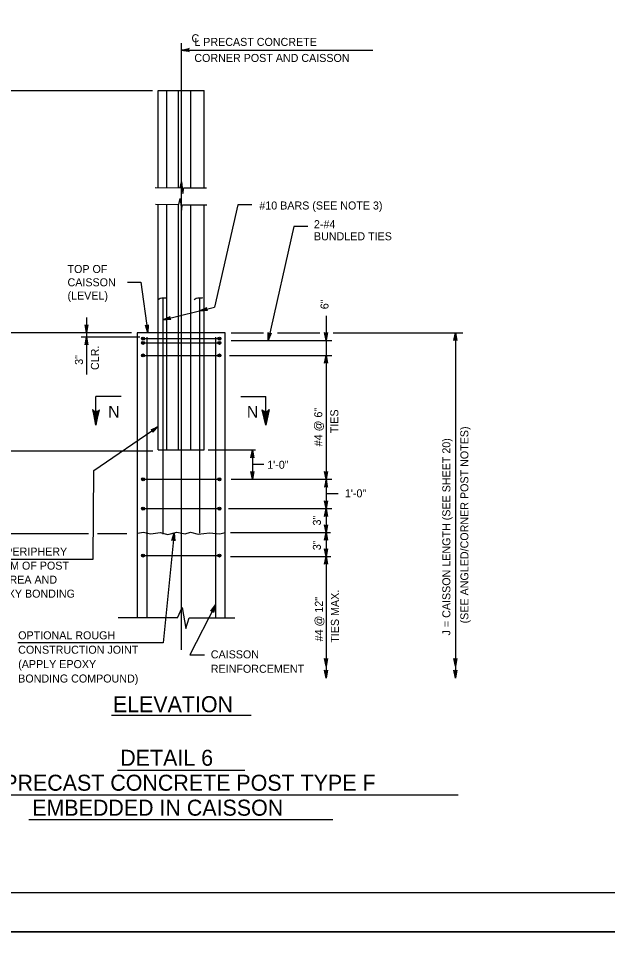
# Model space of a CAD drawing. Extents: x 3351 to 8430, y -3586 to 1457.
# Drawn here: x 4758.6 to 4984.6, y -2999.8 to -2642 of the extents above; entities that cross this region are included whole.
import ezdxf

# ---------------------------------------------------------------- set-up
doc = ezdxf.new("R2010")
doc.units = 0
for name, color, linetype in [('1', 7, 'Continuous'), ('2', 7, 'Continuous'), ('PLT-BNDY', 7, 'Continuous')]:
    doc.layers.add(name, color=color, linetype=linetype)

msp = doc.modelspace()

# ---------------------------------------------------------------- linework, layer by layer
at = {"layer": '1'}
for p, q in [((4821.03, -2651.46), (4821.03, -2884.08)), ((4821.03, -2654.02), (4894.62, -2654.02)), ((4743.72, -2669.51), (4810.02, -2669.51)), ((4812.23, -2669.51), (4829.83, -2669.51)), ((4812.23, -2706.74), (4812.23, -2669.51)), ((4815.43, -2669.51), (4815.43, -2706.84)), ((4819.83, -2669.51), (4819.83, -2706.84)), ((4824.63, -2669.51), (4824.63, -2706.92)), ((4829.83, -2706.92), (4829.83, -2669.51)), ((4812.23, -2762.49), (4812.23, -2713.22)), ((4815.43, -2713.25), (4815.43, -2762.49)), ((4819.83, -2713.29), (4819.83, -2762.49)), ((4824.63, -2713.38), (4824.63, -2762.49)), ((4829.83, -2762.49), (4829.83, -2713.38)), ((4814, -2749.08), (4814, -2839.77)), ((4828.07, -2749.08), (4828.07, -2839.44)), ((4814, -2757.53), (4833.85, -2752.65)), ((4784.67, -2756.6), (4784.67, -2778.51)), ((4876.62, -2756.02), (4876.62, -2818.71)), ((4802, -2762.49), (4743.72, -2762.49)), ((4805.11, -2764.14), (4782.57, -2764.14)), ((4837.86, -2762.49), (4804.11, -2762.49)), ((4804.11, -2762.49), (4804.11, -2871.84)), ((4806.4, -2764.74), (4835.7, -2764.74)), ((4807.83, -2764.14), (4807.83, -2871.9)), ((4812.23, -2807.46), (4812.23, -2762.49)), ((4815.43, -2762.49), (4815.43, -2807.46)), ((4819.83, -2762.49), (4819.83, -2807.46)), ((4824.63, -2762.49), (4824.63, -2807.46)), ((4829.83, -2807.46), (4829.83, -2762.49)), ((4834.24, -2764.14), (4834.24, -2871.9)), ((4837.86, -2871.9), (4837.86, -2762.49)), ((4840.26, -2762.49), (4852.56, -2762.49)), ((4840.26, -2765.43), (4878.88, -2765.43)), ((4858.01, -2762.49), (4874.25, -2762.49)), ((4879.3, -2762.49), (4929.15, -2762.49)), ((4926.26, -2762.43), (4926.26, -2894.96)), ((4806.4, -2766.37), (4835.7, -2766.37)), ((4806.4, -2771.21), (4835.7, -2771.21)), ((4839.54, -2771.21), (4878.88, -2771.21)), ((4797.94, -2786.96), (4788.3, -2786.96)), ((4788.3, -2797.96), (4788.3, -2786.96)), ((4843.85, -2786.96), (4853.5, -2786.96)), ((4853.5, -2797.96), (4853.5, -2786.96)), ((4787.52, -2815.4), (4812.23, -2798.49)), ((4810.15, -2807.89), (4743.72, -2807.89)), ((4812.23, -2807.46), (4829.83, -2807.46)), ((4831.34, -2807.46), (4849.5, -2807.46)), ((4848.35, -2807.46), (4848.35, -2818.71)), ((4787.23, -2849.41), (4787.52, -2815.4)), ((4848.35, -2812.87), (4852.8, -2812.87)), ((4806.4, -2818.71), (4835.7, -2818.71)), ((4840.15, -2818.71), (4878.88, -2818.71)), ((4876.62, -2818.71), (4876.62, -2829.97)), ((4876.62, -2824.2), (4881.32, -2824.2)), ((4806.4, -2829.97), (4835.7, -2829.97)), ((4839.23, -2829.97), (4878.88, -2829.97)), ((4839.23, -2829.97), (4878.88, -2829.97)), ((4876.62, -2829.97), (4876.62, -2839.14)), ((4785.41, -2839.61), (4743.72, -2839.61)), ((4800.18, -2839.61), (4788.86, -2839.61)), ((4804.41, -2839.37), (4806.41, -2838.99)), ((4806.41, -2838.99), (4809.36, -2839.61)), ((4809.36, -2839.61), (4812.92, -2839.07)), ((4812.92, -2839.07), (4815.86, -2839.84)), ((4818.32, -2839.24), (4814.07, -2881.49)), ((4815.86, -2839.84), (4819.35, -2838.99)), ((4819.35, -2838.99), (4822.6, -2839.61)), ((4822.6, -2839.61), (4824.62, -2838.99)), ((4835.91, -2839.62), (4837.86, -2839.14)), ((4840, -2839.14), (4878.34, -2839.14)), ((4876.62, -2839.14), (4876.62, -2848.32)), ((4806.4, -2847.96), (4835.7, -2847.96)), ((4730.59, -2849.41), (4787.23, -2849.41)), ((4840, -2848.32), (4878.43, -2848.32)), ((4876.62, -2848.32), (4876.62, -2894.96)), ((4819.59, -2871.9), (4821.37, -2867.89)), ((4821.37, -2867.89), (4822.78, -2875.99)), ((4834.24, -2866.89), (4824.29, -2886.1)), ((4819.6, -2871.9), (4796.86, -2871.9)), ((4822.78, -2875.99), (4824.04, -2871.9)), ((4824.04, -2871.9), (4841.58, -2871.9)), ((4814.07, -2881.49), (4758.31, -2881.49)), ((4824.29, -2886.1), (4829.97, -2886.1)), ((4794.27, -2909.17), (4847.84, -2909.17)), ((4796.56, -2930.25), (4845.39, -2930.25)), ((4713.79, -2939.76), (4927.27, -2939.76)), ((4762.52, -2949.27), (4879.2, -2949.27))]:
    msp.add_line(p, q, dxfattribs=at)
for points in [[(4821.03, -2654.02), (4824.02, -2653.46), (4823.79, -2653.62), (4823.67, -2653.82), (4823.63, -2654.02), (4823.67, -2654.22), (4823.79, -2654.42), (4824.02, -2654.58), (4821.03, -2654.02), (4823.79, -2654.42), (4823.67, -2654.22), (4821.03, -2654.02), (4823.63, -2654.02), (4823.67, -2653.82), (4821.03, -2654.02), (4823.79, -2653.62)], [(4811.07, -2706.73), (4820.64, -2706.84), (4821.2, -2704.56), (4821.7, -2709.05), (4822.08, -2706.92), (4830.69, -2706.92)], [(4811.11, -2713.2), (4820.07, -2713.3), (4820.64, -2711.02), (4821.14, -2715.51), (4821.52, -2713.38), (4830.8, -2713.38)], [(4848.14, -2713.45), (4842.77, -2713.45), (4833.85, -2752.65)], [(4869.64, -2721.75), (4864.27, -2721.75), (4854.34, -2765.43)], [(4800.47, -2743.05), (4805.57, -2743.05), (4808.25, -2762.49)], [(4828.07, -2754.07), (4830.83, -2752.82), (4830.74, -2752.92), (4830.65, -2753.03), (4830.61, -2753.14), (4830.58, -2753.25), (4830.59, -2753.35), (4830.6, -2753.45), (4830.64, -2753.55), (4830.68, -2753.64), (4830.76, -2753.72), (4830.84, -2753.8), (4830.97, -2753.85), (4831.1, -2753.9), (4828.07, -2754.07), (4830.97, -2753.85), (4830.84, -2753.8), (4828.07, -2754.07), (4830.76, -2753.72), (4830.68, -2753.64), (4828.07, -2754.07), (4830.64, -2753.55), (4830.6, -2753.45), (4828.07, -2754.07), (4830.59, -2753.35), (4830.58, -2753.25), (4828.07, -2754.07), (4830.61, -2753.14), (4830.65, -2753.03), (4828.07, -2754.07), (4830.74, -2752.92)], [(4814, -2757.53), (4816.76, -2756.28), (4816.67, -2756.38), (4816.57, -2756.49), (4816.54, -2756.6), (4816.51, -2756.71), (4816.51, -2756.81), (4816.52, -2756.91), (4816.56, -2757), (4816.6, -2757.1), (4816.68, -2757.18), (4816.76, -2757.26), (4816.89, -2757.31), (4817.02, -2757.36), (4814, -2757.53), (4816.89, -2757.31), (4816.76, -2757.26), (4814, -2757.53), (4816.68, -2757.18), (4816.6, -2757.1), (4814, -2757.53), (4816.56, -2757), (4816.52, -2756.91), (4814, -2757.53), (4816.51, -2756.81), (4816.51, -2756.71), (4814, -2757.53), (4816.54, -2756.6), (4816.57, -2756.49), (4814, -2757.53), (4816.67, -2756.38)], [(4784.67, -2762.49), (4784.11, -2759.5), (4784.27, -2759.73), (4784.47, -2759.85), (4784.67, -2759.89), (4784.87, -2759.85), (4785.07, -2759.73), (4785.23, -2759.5), (4784.67, -2762.49), (4785.07, -2759.73), (4784.87, -2759.85), (4784.67, -2762.49), (4784.67, -2759.89), (4784.47, -2759.85), (4784.67, -2762.49), (4784.27, -2759.73)], [(4808.25, -2762.49), (4807.29, -2759.61), (4807.48, -2759.82), (4807.7, -2759.91), (4807.9, -2759.91), (4808.09, -2759.85), (4808.27, -2759.71), (4808.4, -2759.46), (4808.25, -2762.49), (4808.27, -2759.71), (4808.09, -2759.85), (4808.25, -2762.49), (4807.9, -2759.91), (4807.7, -2759.91), (4808.25, -2762.49), (4807.48, -2759.82)], [(4784.67, -2764.14), (4785.23, -2767.12), (4785.07, -2766.89), (4784.87, -2766.77), (4784.67, -2766.74), (4784.47, -2766.77), (4784.27, -2766.89), (4784.11, -2767.12), (4784.67, -2764.14), (4784.27, -2766.89), (4784.47, -2766.77), (4784.67, -2764.14), (4784.67, -2766.74), (4784.87, -2766.77), (4784.67, -2764.14), (4785.07, -2766.89)], [(4854.34, -2765.43), (4854.45, -2762.4), (4854.56, -2762.66), (4854.72, -2762.82), (4854.91, -2762.9), (4855.11, -2762.91), (4855.34, -2762.83), (4855.54, -2762.65), (4854.34, -2765.43), (4855.34, -2762.83), (4855.11, -2762.91), (4854.34, -2765.43), (4854.91, -2762.9), (4854.72, -2762.82), (4854.34, -2765.43), (4854.56, -2762.66)], [(4876.62, -2765.43), (4876.06, -2762.45), (4876.22, -2762.68), (4876.42, -2762.8), (4876.62, -2762.83), (4876.82, -2762.8), (4877.02, -2762.68), (4877.18, -2762.45), (4876.62, -2765.43), (4877.02, -2762.68), (4876.82, -2762.8), (4876.62, -2765.43), (4876.62, -2762.83), (4876.42, -2762.8), (4876.62, -2765.43), (4876.22, -2762.68)], [(4926.26, -2762.43), (4926.82, -2765.42), (4926.66, -2765.19), (4926.46, -2765.07), (4926.26, -2765.03), (4926.06, -2765.07), (4925.86, -2765.19), (4925.7, -2765.42), (4926.26, -2762.43), (4925.86, -2765.19), (4926.06, -2765.07), (4926.26, -2762.43), (4926.26, -2765.03), (4926.46, -2765.07), (4926.26, -2762.43), (4926.66, -2765.19)], [(4876.62, -2771.21), (4877.18, -2774.19), (4877.02, -2773.96), (4876.82, -2773.84), (4876.62, -2773.81), (4876.42, -2773.84), (4876.22, -2773.96), (4876.06, -2774.19), (4876.62, -2771.21), (4876.22, -2773.96), (4876.42, -2773.84), (4876.62, -2771.21), (4876.62, -2773.81), (4876.82, -2773.84), (4876.62, -2771.21), (4877.02, -2773.96)], [(4788.3, -2797.96), (4789.71, -2792.01), (4789.52, -2792.24), (4789.33, -2792.47), (4789.08, -2792.58), (4788.84, -2792.7), (4788.6, -2792.73), (4788.36, -2792.76), (4788.12, -2792.73), (4787.88, -2792.69), (4787.64, -2792.57), (4787.41, -2792.45), (4787.22, -2792.22), (4787.03, -2791.99), (4788.3, -2797.96), (4787.22, -2792.22), (4787.41, -2792.45), (4788.3, -2797.96), (4787.64, -2792.57), (4787.88, -2792.69), (4788.3, -2797.96), (4788.12, -2792.73), (4788.36, -2792.76), (4788.3, -2797.96), (4788.6, -2792.73), (4788.84, -2792.7), (4788.3, -2797.96), (4789.08, -2792.58), (4789.33, -2792.47), (4788.3, -2797.96), (4789.52, -2792.24)], [(4853.5, -2797.96), (4852.08, -2792.01), (4852.27, -2792.24), (4852.47, -2792.47), (4852.71, -2792.58), (4852.95, -2792.7), (4853.19, -2792.73), (4853.43, -2792.76), (4853.67, -2792.73), (4853.91, -2792.69), (4854.15, -2792.57), (4854.39, -2792.45), (4854.58, -2792.22), (4854.76, -2791.99), (4853.5, -2797.96), (4854.58, -2792.22), (4854.39, -2792.45), (4853.5, -2797.96), (4854.15, -2792.57), (4853.91, -2792.69), (4853.5, -2797.96), (4853.67, -2792.73), (4853.43, -2792.76), (4853.5, -2797.96), (4853.19, -2792.73), (4852.95, -2792.7), (4853.5, -2797.96), (4852.71, -2792.58), (4852.47, -2792.47), (4853.5, -2797.96), (4852.27, -2792.24)], [(4812.23, -2798.49), (4810.09, -2800.64), (4810.19, -2800.38), (4810.17, -2800.14), (4810.09, -2799.96), (4809.95, -2799.81), (4809.74, -2799.72), (4809.46, -2799.71), (4812.23, -2798.49), (4809.74, -2799.72), (4809.95, -2799.81), (4812.23, -2798.49), (4810.09, -2799.96), (4810.17, -2800.14), (4812.23, -2798.49), (4810.19, -2800.38)], [(4848.35, -2807.46), (4848.91, -2810.44), (4848.75, -2810.21), (4848.55, -2810.09), (4848.35, -2810.06), (4848.15, -2810.09), (4847.95, -2810.21), (4847.79, -2810.44), (4848.35, -2807.46), (4847.95, -2810.21), (4848.15, -2810.09), (4848.35, -2807.46), (4848.35, -2810.06), (4848.55, -2810.09), (4848.35, -2807.46), (4848.75, -2810.21)], [(4848.35, -2818.71), (4847.79, -2815.73), (4847.95, -2815.96), (4848.15, -2816.08), (4848.35, -2816.11), (4848.55, -2816.08), (4848.75, -2815.96), (4848.91, -2815.73), (4848.35, -2818.71), (4848.75, -2815.96), (4848.55, -2816.08), (4848.35, -2818.71), (4848.35, -2816.11), (4848.15, -2816.08), (4848.35, -2818.71), (4847.95, -2815.96)], [(4876.62, -2818.71), (4876.06, -2815.73), (4876.22, -2815.96), (4876.42, -2816.08), (4876.62, -2816.11), (4876.82, -2816.08), (4877.02, -2815.96), (4877.18, -2815.73), (4876.62, -2818.71), (4877.02, -2815.96), (4876.82, -2816.08), (4876.62, -2818.71), (4876.62, -2816.11), (4876.42, -2816.08), (4876.62, -2818.71), (4876.22, -2815.96)], [(4876.62, -2818.71), (4876.06, -2821.7), (4876.22, -2821.47), (4876.42, -2821.35), (4876.62, -2821.31), (4876.82, -2821.35), (4877.02, -2821.47), (4877.18, -2821.7), (4876.62, -2818.71), (4877.02, -2821.47), (4876.82, -2821.35), (4876.62, -2818.71), (4876.62, -2821.31), (4876.42, -2821.35), (4876.62, -2818.71), (4876.22, -2821.47)], [(4876.62, -2829.97), (4876.06, -2826.98), (4876.22, -2827.21), (4876.42, -2827.33), (4876.62, -2827.37), (4876.82, -2827.33), (4877.02, -2827.21), (4877.18, -2826.98), (4876.62, -2829.97), (4877.02, -2827.21), (4876.82, -2827.33), (4876.62, -2829.97), (4876.62, -2827.37), (4876.42, -2827.33), (4876.62, -2829.97), (4876.22, -2827.21)], [(4876.62, -2829.97), (4877.18, -2832.95), (4877.02, -2832.72), (4876.82, -2832.6), (4876.62, -2832.57), (4876.42, -2832.6), (4876.22, -2832.72), (4876.06, -2832.95), (4876.62, -2829.97), (4876.22, -2832.72), (4876.42, -2832.6), (4876.62, -2829.97), (4876.62, -2832.57), (4876.82, -2832.6), (4876.62, -2829.97), (4877.02, -2832.72)], [(4876.62, -2839.14), (4876.06, -2836.16), (4876.22, -2836.39), (4876.42, -2836.51), (4876.62, -2836.54), (4876.82, -2836.51), (4877.02, -2836.39), (4877.18, -2836.16), (4876.62, -2839.14), (4877.02, -2836.39), (4876.82, -2836.51), (4876.62, -2839.14), (4876.62, -2836.54), (4876.42, -2836.51), (4876.62, -2839.14), (4876.22, -2836.39)], [(4818.32, -2839.24), (4818.58, -2842.26), (4818.44, -2842.02), (4818.26, -2841.88), (4818.06, -2841.83), (4817.86, -2841.84), (4817.65, -2841.94), (4817.46, -2842.15), (4818.32, -2839.24), (4817.65, -2841.94), (4817.86, -2841.84), (4818.32, -2839.24), (4818.06, -2841.83), (4818.26, -2841.88), (4818.32, -2839.24), (4818.44, -2842.02)], [(4824.62, -2838.99), (4827.55, -2839.7), (4831.84, -2839.28), (4835.91, -2839.62)], [(4876.62, -2839.14), (4877.18, -2842.12), (4877.02, -2841.89), (4876.82, -2841.78), (4876.62, -2841.74), (4876.42, -2841.78), (4876.22, -2841.89), (4876.06, -2842.12), (4876.62, -2839.14), (4876.22, -2841.89), (4876.42, -2841.78), (4876.62, -2839.14), (4876.62, -2841.74), (4876.82, -2841.78), (4876.62, -2839.14), (4877.02, -2841.89)], [(4876.62, -2848.32), (4876.06, -2845.34), (4876.22, -2845.57), (4876.42, -2845.68), (4876.62, -2845.72), (4876.82, -2845.68), (4877.02, -2845.57), (4877.18, -2845.34), (4876.62, -2848.32), (4877.02, -2845.57), (4876.82, -2845.68), (4876.62, -2848.32), (4876.62, -2845.72), (4876.42, -2845.68), (4876.62, -2848.32), (4876.22, -2845.57)], [(4876.62, -2848.32), (4877.18, -2851.3), (4877.02, -2851.07), (4876.82, -2850.95), (4876.62, -2850.92), (4876.42, -2850.95), (4876.22, -2851.07), (4876.06, -2851.3), (4876.62, -2848.32), (4876.22, -2851.07), (4876.42, -2850.95), (4876.62, -2848.32), (4876.62, -2850.92), (4876.82, -2850.95), (4876.62, -2848.32), (4877.02, -2851.07)], [(4834.24, -2866.89), (4833.36, -2869.79), (4833.35, -2869.65), (4833.33, -2869.52), (4833.27, -2869.42), (4833.2, -2869.32), (4833.12, -2869.26), (4833.04, -2869.2), (4832.95, -2869.17), (4832.85, -2869.14), (4832.73, -2869.14), (4832.62, -2869.15), (4832.49, -2869.21), (4832.37, -2869.28), (4834.24, -2866.89), (4832.49, -2869.21), (4832.62, -2869.15), (4834.24, -2866.89), (4832.73, -2869.14), (4832.85, -2869.14), (4834.24, -2866.89), (4832.95, -2869.17), (4833.04, -2869.2), (4834.24, -2866.89), (4833.12, -2869.26), (4833.2, -2869.32), (4834.24, -2866.89), (4833.27, -2869.42), (4833.33, -2869.52), (4834.24, -2866.89), (4833.35, -2869.65)], [(4876.62, -2890.41), (4876.06, -2887.43), (4876.22, -2887.66), (4876.42, -2887.77), (4876.62, -2887.81), (4876.82, -2887.77), (4877.02, -2887.66), (4877.18, -2887.43), (4876.62, -2890.41), (4877.02, -2887.66), (4876.82, -2887.77), (4876.62, -2890.41), (4876.62, -2887.81), (4876.42, -2887.77), (4876.62, -2890.41), (4876.22, -2887.66)], [(4926.26, -2890.41), (4925.7, -2887.43), (4925.86, -2887.66), (4926.06, -2887.77), (4926.26, -2887.81), (4926.46, -2887.77), (4926.66, -2887.66), (4926.82, -2887.43), (4926.26, -2890.41), (4926.66, -2887.66), (4926.46, -2887.77), (4926.26, -2890.41), (4926.26, -2887.81), (4926.06, -2887.77), (4926.26, -2890.41), (4925.86, -2887.66)], [(4876.62, -2894.96), (4876.06, -2891.98), (4876.22, -2892.21), (4876.42, -2892.33), (4876.62, -2892.36), (4876.82, -2892.33), (4877.02, -2892.21), (4877.18, -2891.98), (4876.62, -2894.96), (4877.02, -2892.21), (4876.82, -2892.33), (4876.62, -2894.96), (4876.62, -2892.36), (4876.42, -2892.33), (4876.62, -2894.96), (4876.22, -2892.21)], [(4926.26, -2894.96), (4925.7, -2891.98), (4925.86, -2892.21), (4926.06, -2892.33), (4926.26, -2892.36), (4926.46, -2892.33), (4926.66, -2892.21), (4926.82, -2891.98), (4926.26, -2894.96), (4926.66, -2892.21), (4926.46, -2892.33), (4926.26, -2894.96), (4926.26, -2892.36), (4926.06, -2892.33), (4926.26, -2894.96), (4925.86, -2892.21)]]:
    msp.add_lwpolyline(points, dxfattribs=at)
for centre, radius in [((4806.4, -2764.74), 0.585), ((4806.4, -2766.37), 0.585), ((4806.4, -2764.74), 0.442), ((4806.4, -2764.74), 0.316), ((4806.4, -2764.74), 0.179), ((4835.7, -2764.74), 0.585), ((4835.7, -2766.37), 0.585), ((4835.7, -2764.74), 0.442), ((4835.7, -2764.74), 0.316), ((4835.7, -2764.74), 0.179), ((4806.4, -2766.37), 0.442), ((4806.4, -2766.37), 0.316), ((4806.4, -2766.37), 0.179), ((4835.7, -2766.37), 0.442), ((4835.7, -2766.37), 0.316), ((4835.7, -2766.37), 0.179), ((4806.4, -2771.21), 0.585), ((4806.4, -2771.21), 0.442), ((4806.4, -2771.21), 0.316), ((4806.4, -2771.21), 0.179), ((4835.7, -2771.21), 0.585), ((4835.7, -2771.21), 0.442), ((4835.7, -2771.21), 0.316), ((4835.7, -2771.21), 0.179), ((4806.4, -2818.71), 0.585), ((4806.4, -2818.71), 0.442), ((4806.4, -2818.71), 0.316), ((4806.4, -2818.71), 0.179), ((4835.7, -2818.71), 0.585), ((4835.7, -2818.71), 0.442), ((4835.7, -2818.71), 0.316), ((4835.7, -2818.71), 0.179), ((4806.4, -2829.96), 0.585), ((4806.4, -2829.96), 0.442), ((4806.4, -2829.96), 0.316), ((4806.4, -2829.96), 0.179), ((4835.7, -2829.96), 0.585), ((4835.7, -2829.96), 0.442), ((4835.7, -2829.96), 0.316), ((4835.7, -2829.96), 0.179), ((4806.4, -2847.96), 0.585), ((4806.4, -2847.96), 0.442), ((4806.4, -2847.96), 0.316), ((4806.4, -2847.96), 0.179), ((4835.7, -2847.96), 0.585), ((4835.7, -2847.96), 0.442), ((4835.7, -2847.96), 0.316), ((4835.7, -2847.96), 0.179)]:
    msp.add_circle(centre, radius, dxfattribs=at)
for points in [[(4812.23, -2749.71), (4813.01, -2749.2), (4814.18, -2749.09), (4814.88, -2749.13), (4815.54, -2748.93)], [(4826.05, -2749.7), (4826.83, -2749.2), (4827.99, -2749.08), (4828.69, -2749.12), (4829.36, -2748.92)]]:
    msp.add_spline(points, degree=3, dxfattribs=at)
at = {"layer": '2'}
msp.add_line((5428.34, -2977.31), (4642.34, -2977.31), dxfattribs=at)
at = {"layer": 'PLT-BNDY'}
for points in [[(4602.34, -2398.31), (5443.34, -2398.31), (5443.34, -2992.31), (4602.34, -2992.31)], [(4602.34, -2992.31), (5443.34, -2992.31), (5443.34, -3586.31), (4602.34, -3586.31)]]:
    msp.add_lwpolyline(points, close=True, dxfattribs=at)

# ---------------------------------------------------------------- texts
at = {"layer": '1'}
for s, height, p in [('C', 3.07, (4824.98, -2651.05)), ('L PRECAST CONCRETE', 3.072, (4826.06, -2652.45)), ('CORNER POST AND CAISSON', 3.072, (4826.06, -2658.6)), ('#10 BARS (SEE NOTE 3)', 3.072, (4851.02, -2715.21)), ('2-#4', 3.072, (4871.97, -2722.37)), ('BUNDLED TIES', 3.072, (4871.97, -2727.02)), ('TOP OF', 3.072, (4777.4, -2739.57)), ('CAISSON', 3.072, (4777.4, -2744.67)), ('(LEVEL)', 3.072, (4777.4, -2749.77)), ('N', 4.48, (4793.01, -2795.03)), ('N', 4.48, (4846.24, -2795.03)), ('1\'-0"', 3.072, (4854.04, -2814.68)), ('1\'-0"', 3.072, (4883.84, -2825.64)), ('ROUGHEN PERIPHERY', 3.072, (4731.39, -2847.99)), ('AND BOTTOM OF POST', 3.072, (4731.39, -2853.37)), ('CONTACT AREA AND', 3.072, (4731.39, -2858.75)), ('APPLY EPOXY BONDING', 3.072, (4731.39, -2864.12)), ('OPTIONAL ROUGH', 3.072, (4758.47, -2880.1)), ('CONSTRUCTION JOINT', 3.072, (4758.47, -2885.63)), ('CAISSON', 3.072, (4832.39, -2887.41)), ('(APPLY EPOXY', 3.072, (4758.47, -2891.15)), ('REINFORCEMENT', 3.072, (4832.39, -2892.94)), ('BONDING COMPOUND)', 3.072, (4758.47, -2896.68)), ('ELEVATION', 6.144, (4794.8, -2908.06)), ('DETAIL 6', 6.144, (4797.64, -2928.61)), ('CORNER PRECAST CONCRETE POST TYPE F', 6.1439, (4714.84, -2938.19)), ('EMBEDDED IN CAISSON', 6.1439, (4763.85, -2947.77))]:
    msp.add_text(s, height=height, dxfattribs=at).set_placement(p)
for s, p in [('6"', (4877.57, -2753.46)), ('CLR.', (4789.45, -2776.8)), ('3"', (4783.31, -2774.8)), ('#4 @ 6"', (4875.17, -2806.05)), ('TIES', (4881.32, -2801.05)), ('(SEE ANGLED/CORNER POST NOTES)', (4931.24, -2873.99)), ('J = CAISSON LENGTH (SEE SHEET 20)', (4924.32, -2878.61)), ('3"', (4874.63, -2836.43)), ('3"', (4874.63, -2845.9)), ('TIES MAX.', (4881.54, -2881.41)), ('#4 @ 12"', (4875.39, -2880.89))]:
    msp.add_text(s, height=3.072, rotation=90, dxfattribs=at).set_placement(p)

doc.saveas('drawing.dxf')
